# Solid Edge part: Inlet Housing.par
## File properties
Title: Inlet Housing
Author: Dan
Template: Normal.par
Last saved by: Dan
Revision: 54
Application: Solid Edge
Density: 0 kg/mm^3
Accuracy: 0.99
Document Number: P52-002
Project Name: Piston Pump P52
Material: aluminum
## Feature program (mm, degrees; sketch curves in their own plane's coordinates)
sketch for "unnamed Protrusion 1" plane through (0, 0, 0) normal (0, 0, 1) x-axis (1, 0, 0)
  line (0, 56.1155) -> (-40.7327, 53.9808)
  arc centre (-40, 40) radius 14 from (-53.9867, 39.3893) to (-40.7327, 53.9808) cw
  line (-52.2669, 0) -> (-53.9867, 39.3893)
  line (-52.2669, 0) -> (-53.9867, -39.3893)
  arc centre (-40, -40) radius 14 from (-40.7327, -53.9808) to (-53.9867, -39.3893) cw
  line (0, -56.1155) -> (-40.7327, -53.9808)
  line (0, -56.1155) -> (40.7327, -53.9808)
  arc centre (40, -40) radius 14 from (53.9867, -39.3893) to (40.7327, -53.9808) cw
  line (52.2669, 0) -> (53.9867, -39.3893)
  line (52.2669, 0) -> (53.9867, 39.3893)
  arc centre (40, 40) radius 14 from (40.7327, 53.9808) to (53.9867, 39.3893) cw
  line (0, 56.1155) -> (40.7327, 53.9808)
extrude "unnamed Protrusion 1" add finite 150.5 along +normal
sketch for "unnamed RevolvedCutout 1" plane through (54, 0, 0) normal (1, 0, 0) x-axis (0, 1, 0)
  line (-53.9808, 134.5) -> (-19.9808, 134.5)
  arc centre (-19.9808, 130.5) radius 4 from (-19.9808, 134.5) to (-15.9808, 130.5) cw
  line (-15.9808, 130.5) -> (-15.9808, 122.5)
  arc centre (-17.9808, 122.5) radius 2 from (-15.9808, 122.5) to (-17.1356, 120.6874) cw
  line (-17.1356, 120.6874) -> (-39.7933, 110.1219)
  line (-39.7933, 110.1219) -> (-53.9808, 9.1723)
revolve "unnamed RevolvedCutout 1" cut full turn 360 deg about sketch line (-53.9808, 134.5) -> (-53.9808, 9.1723)
sketch for "ExtrudedCutout_1" plane through (0, 0, 0) normal (-0.707107, -0.707107, 0) x-axis (0, 0, 1)
  line (36.266, -72.5462) -> (113.5032, -61.6912)
  line (113.5032, -61.6912) -> (117.3683, -72.8715)
extrude "ExtrudedCutout_1" cut finite 95.25 symmetric
fillet "Round_1" radius 3
pattern "unnamed Pattern 1" of "unnamed RevolvedCutout 1", "ExtrudedCutout_1", "Round_1"
revolve "unnamed RevolvedCutout 2" cut full turn 360 deg
extrude "unnamed Cutout 1" cut finite 95.25 symmetric
fillet "unnamed Round 1"
revolve "unnamed RevolvedCutout 3" cut full turn 360 deg
extrude "unnamed Cutout 2" cut finite 95.25 symmetric
fillet "unnamed Round 2"
revolve "unnamed RevolvedCutout 4" cut full turn 360 deg
extrude "unnamed Cutout 3" cut finite 95.25 symmetric
fillet "unnamed Round 3"
sketch for "ExtrudedProtrusion_2" plane through (0, 0, 150.5) normal (0, 0, 1) x-axis (1, 0, 0)
  circle centre (0, 0) radius 40
extrude "ExtrudedProtrusion_2" add finite 8.5 along +normal
chamfer "Chamfer_1" setback 2
sketch for "Hole_1" plane through (0, 0, 150.5) normal (0, 0, 1) x-axis (1, 0, 0)
  hole centre (40, 40) bore radius 6.25
hole "Hole_1" diameter 12.5 through
sketch for "unnamed Hole 1" plane through (0, 0, 150.5) normal (0, 0, 1) x-axis (1, 0, 0)
  hole centre (40, -40) bore radius 6.25
hole "unnamed Hole 1" through
sketch for "unnamed Hole 2" plane through (0, 0, 150.5) normal (0, 0, 1) x-axis (1, 0, 0)
  hole centre (-40, -40) bore radius 6.25
hole "unnamed Hole 2" through
sketch for "unnamed Hole 3" plane through (0, 0, 150.5) normal (0, 0, 1) x-axis (1, 0, 0)
  hole centre (-40, 40) bore radius 6.25
hole "unnamed Hole 3" through
pattern "unnamed Pattern 2" of "Hole_1", "unnamed Hole 1", "unnamed Hole 2", "unnamed Hole 3"
sketch for "unnamed RevolvedCutout 5" plane through (0, 0, 0) normal (1, 0, 0) x-axis (0, 1, 0)
  line (35, 155.5) -> (35, 159)
  line (26, 155.5) -> (35, 155.5)
  line (26, 139) -> (26, 155.5)
  line (24.01, 139) -> (26, 139)
  line (24.01, 136) -> (24.01, 139)
  line (27.5, 136) -> (24.01, 136)
  line (27.5, 115.2) -> (27.5, 136)
  line (27.5, 115.2) -> (28.7, 114)
  line (41.5, 114) -> (28.7, 114)
  line (41.5, 112) -> (41.5, 114)
  line (43, 112) -> (41.5, 112)
  arc centre (43, 109) radius 3 from (43, 112) to (46, 109) cw
  line (46, 89) -> (46, 109)
  line (47, 88) -> (46, 89)
  line (47, 2.3) -> (47, 88)
  line (48.4, 2.3) -> (47, 2.3)
  line (48.4, 0.6364) -> (48.4, 2.3)
  line (48.4, 0.6364) -> (49.0364, 0)
  dimension (linear) = 28.7
revolve "unnamed RevolvedCutout 5" cut full turn 360 deg
sketch for "ExtrudedProtrusion_3" plane through (0, 53.9808, 0) normal (0, -1, 0) x-axis (1, 0, 0)
  circle centre (0, 57) radius 30
extrude "ExtrudedProtrusion_3" add finite 30 along -normal
fillet "Round_5" radius 5
chamfer "Chamfer_2" setback 2
sketch for "Hole_5" plane through (0, 83.9808, 37.2585) normal (0, 1, 0) x-axis (-1, 0, 0)
hole "Hole_5" diameter 33.5 through
sketch for "v_1" plane through (0, 83.9808, 37.2585) normal (0, 1, 0) x-axis (-1, 0, 0)
hole "v_1" finite
sketch for "ExtrudedProtrusion_4" plane through (0, 0, 0) normal (1, 0, 0) x-axis (0, 1, 0)
extrude "ExtrudedProtrusion_4" add finite 10 symmetric
sketch for "ExtrudedProtrusion_5" plane through (0, 0, 0) normal (1, 0, 0) x-axis (0, 1, 0)
extrude "ExtrudedProtrusion_5" add finite 10 symmetric
fillet "Round_6" radius 2
sketch for "unnamed Hole 4" plane through (0, 0, 0) normal (0, 0, 1) x-axis (1, 0, 0)
hole "unnamed Hole 4" finite
sketch for "Hole_7" plane through (0, 0, 0) normal (0, 0, 1) x-axis (1, 0, 0)
hole "Hole_7" finite
sketch for "unnamed Hole 5" plane through (0, 0, 0) normal (0, 0, 1) x-axis (1, 0, 0)
  hole centre (40, -40) bore radius 5.1
hole "unnamed Hole 5" finite
sketch for "unnamed Hole 6" plane through (0, 0, 0) normal (0, 0, 1) x-axis (1, 0, 0)
  hole centre (-40, -40) bore radius 5.1
hole "unnamed Hole 6" finite
pattern "unnamed Pattern 3" of "unnamed Hole 4", "Hole_7", "unnamed Hole 5", "unnamed Hole 6"
sketch for "unnamed Protrusion 2" plane through (0, 0, 0) normal (0, 0, 1) x-axis (1, 0, 0)
extrude "unnamed Protrusion 2" add finite 5 along +normal
mirror "unnamed Mirror 1" of "unnamed Protrusion 2" about plane through (0, 0, 0) normal (1, 0, 0)
extrude "unnamed Protrusion 3" add finite 5
sketch for "ExtrudedCutout_5" plane through (0, 0, 57) normal (0, 0, 1) x-axis (1, 0, 0)
  line (-36.7082, 32.1081) -> (-38.9457, 19.4187)
  line (-38.9457, 19.4187) -> (38.9457, 19.4187)
  line (36.7082, 32.1081) -> (38.9457, 19.4187)
  arc centre (24.8906, 30.0243) radius 12 from (36.7082, 32.1081) to (32.5492, 39.2626) ccw
  arc centre (0, 0) radius 51 from (32.5492, 39.2626) to (-32.5492, 39.2626) ccw
  arc centre (-24.8906, 30.0243) radius 12 from (-32.5492, 39.2626) to (-36.7082, 32.1081) ccw
  dimension (linear) = 0.0002
extrude "ExtrudedCutout_5" cut finite 34 symmetric
fillet "Round_7" radius 3
fillet "Round_8" radius 6
sketch for "Hole_11" plane through (0, -55, 0) normal (0, -1, 0) x-axis (1, 0, 0)
  hole centre (0, 58) bore radius 2.4585
hole "Hole_11" through  VBottomAngle = 118 deg; Plane_Distance = 55 mm
sketch for "Hole_12" plane through (0, 0, 0) normal (0, -1, 0) x-axis (1, 0, 0)
hole "Hole_12" diameter 3.5 through  VBottomAngle = 118 deg
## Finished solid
Body 1: solid body, 207 faces, 446 edges, 234 vertices.
  Faces by surface: cylinder 75, blend 48, plane 42, torus 21, cone 13, sphere 8
  Edges by curve: circle 195, line 133, intersection 92, ellipse 26
Bounding box of the edges (mm; curved faces can reach further): 108.000 x 140.096 x 159.000, from (-54, -56.1155, 0) to (54, 83.9808, 159).
Cylindrical faces by radius (mm): R1.75 x1, R2 x8, R2.4585 x1, R3 x28, R5.1 x4, R6.25 x4, R7.5 x1, R12 x2, R14 x8, R16.75 x1, R19.476 x1, R24.01 x1, R26 x1, R27.5 x1, R30 x1, R35 x1, R38 x4, R40 x1, R41.5 x1, R46 x1, R47 x1, R48.4 x1, R51 x2
Conical faces (half-angle, radius in mm at the cone's reference point): 45 deg R27.5 x1, 45 deg R28 x1, 45 deg R40 x1, 45 deg R46 x1, 45 deg R48.4 x1, 59 deg R5.1 x4, 65 deg R36.8452 x4
Toroidal faces (ring radius, tube radius in mm): R9 r3 x4, R11 r3 x4, R34 r4 x4, R36 r2 x4, R43 r3 x1, R48 r3 x4
Spherical faces by radius (mm): R3 x8
Planar faces by outward normal: +x 3, +y 2, +z 7, -x 3, -y 1, -z 10, oblique 16
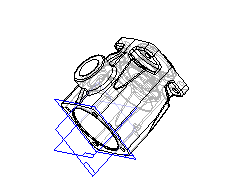
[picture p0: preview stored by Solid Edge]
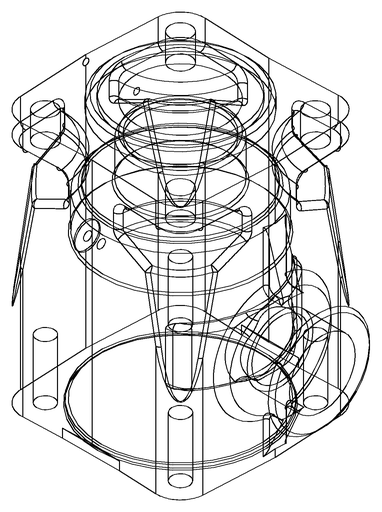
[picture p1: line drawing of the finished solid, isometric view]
